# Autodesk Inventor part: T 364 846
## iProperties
Company: Mayer & Müller AG Schaltgeräte
Created: 2006-07
Part Number: T 364 846
Material: 1.0120
Document SubType Name: Modeling
Designer: I.Baliuc
Manufacturer: Standard
Standards Organization: Custom
Description: Seitenteil, Trenner
Density: 7.85 g/cm^3
HalbzeugNorm: DIN 174
Zweck: Antriebseite: Motor-Standard
Abmessung: Fl. 120x12-525
Author: T.Messerschmitt
Revision Number: 364846
Keywords: 380125
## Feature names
1. Extrusion2
2. Bohrung_Ø13 [Hole]
3. Bohrung2 [Hole]
4. Bohrung3 [Hole]
5. Bohrung_M8 [Hole]
6. Bohrung_Ø36 [Hole]
7. Bohrung_Ø5.5 [Hole]
8. Bohrung_Ø12 [Hole]
9. Bohrung_Ø2 [Hole]
